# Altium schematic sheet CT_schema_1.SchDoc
size 457 x 258 mm
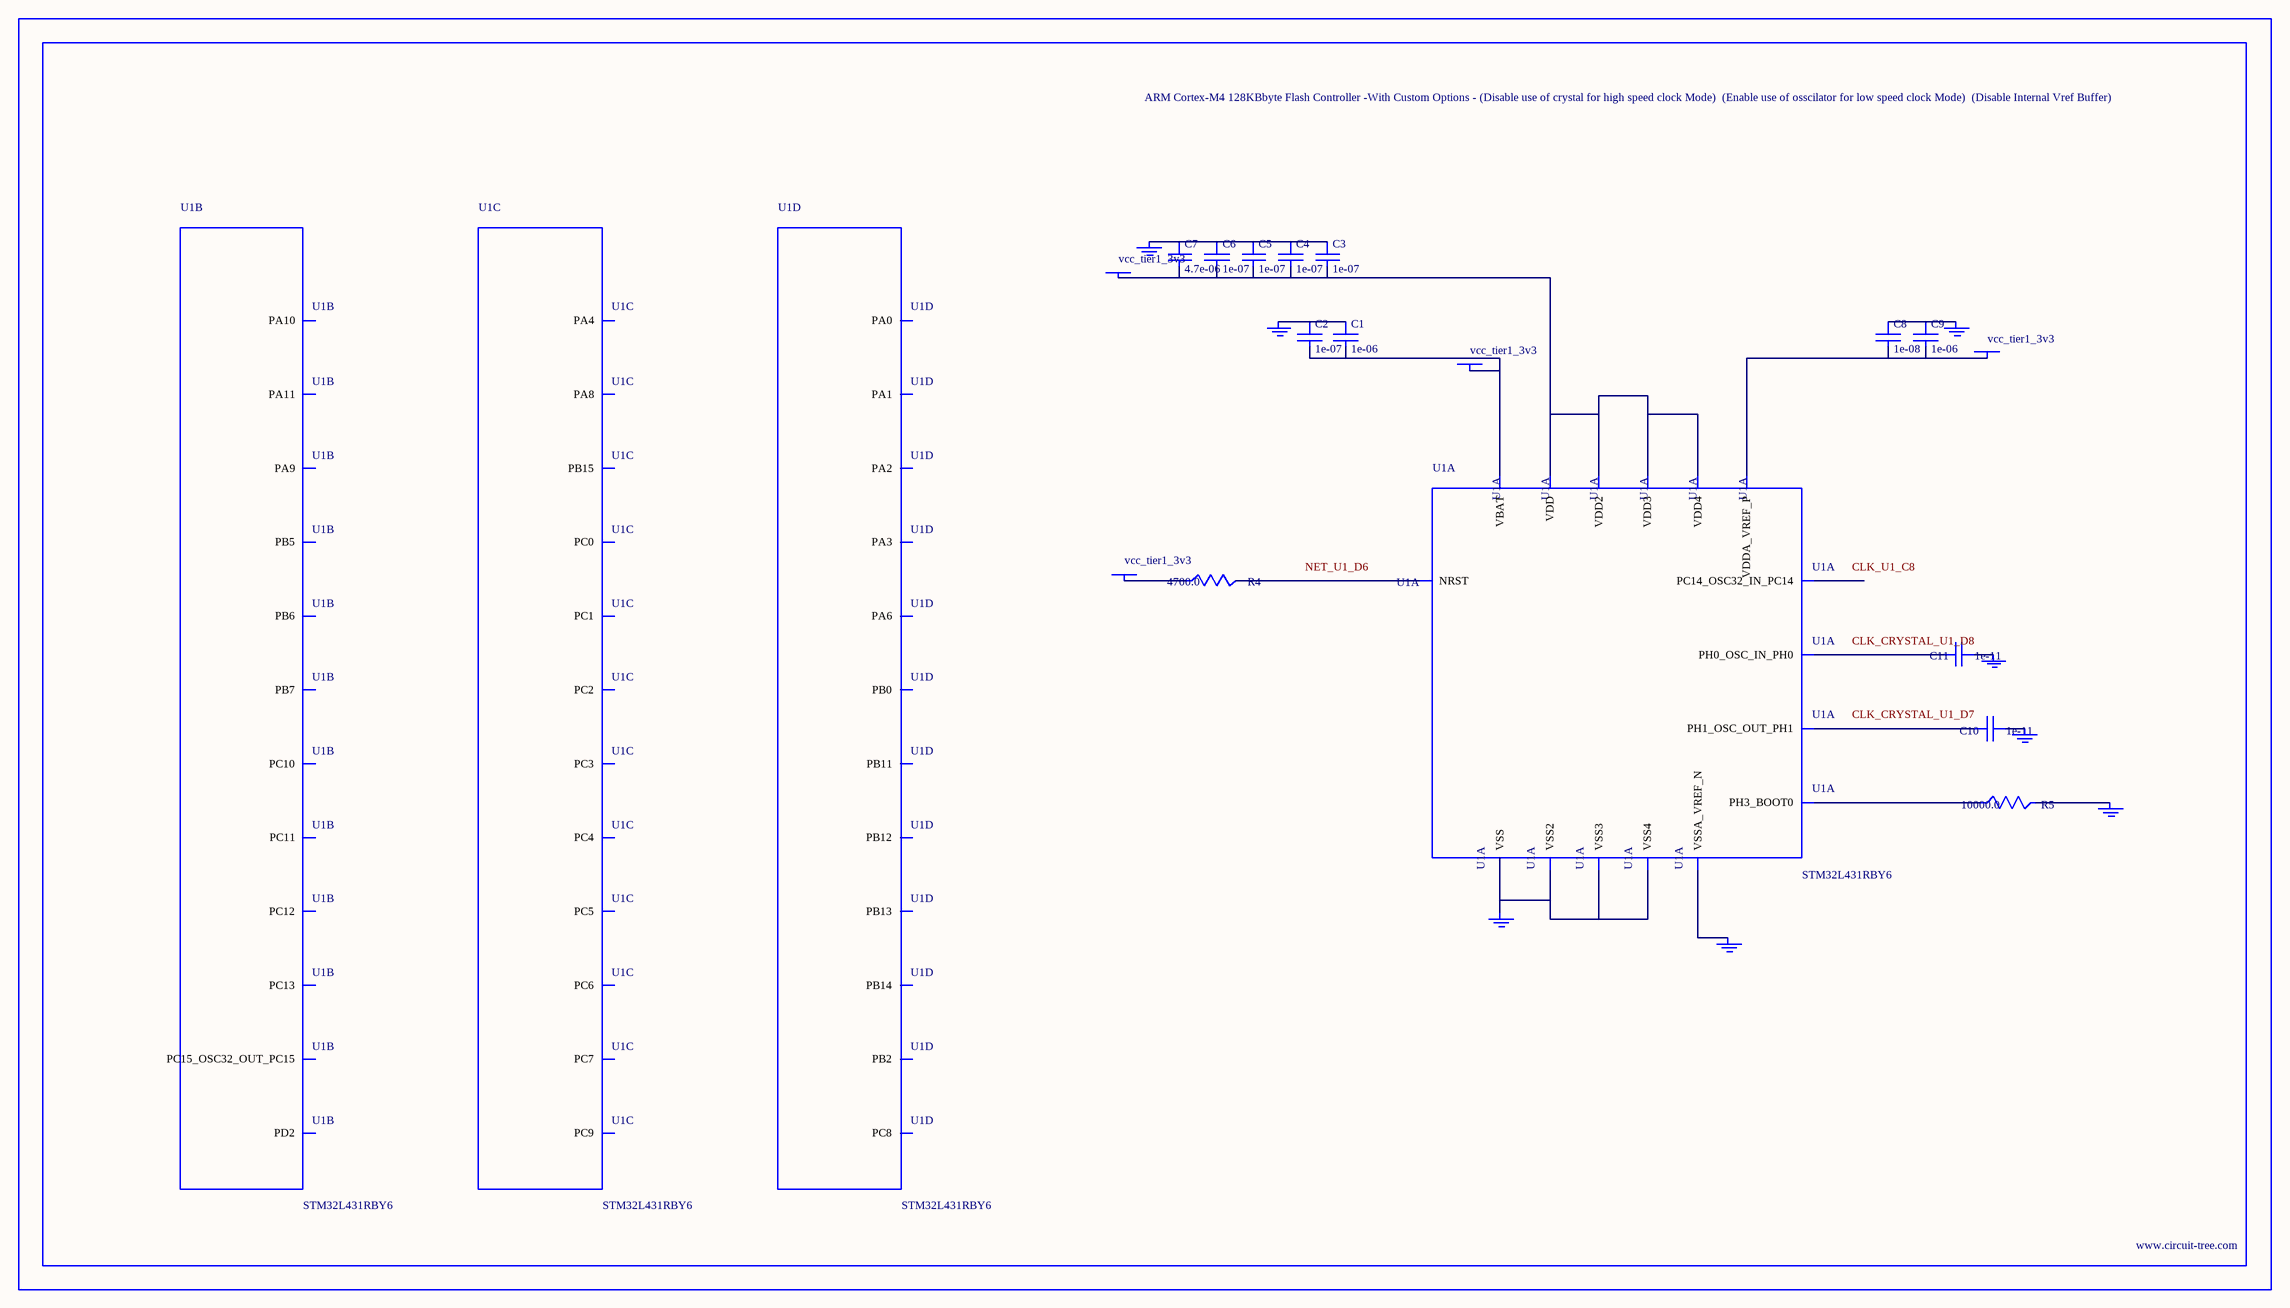
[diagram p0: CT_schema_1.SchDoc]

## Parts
BORDER0  (no value)
C1  1e-06  [C0603]
C2  1e-07  [C0603]
C3  1e-07  [C0603]
C4  1e-07  [C0603]
C5  1e-07  [C0603]
C6  1e-07  [C0603]
C7  4.7e-06  [C0603]
C8  1e-08  [C0603]
C9  1e-06  [C0603]
C10  1e-11  [C0402]
C11  1e-11  [C0402]
GND_INSTANCE_0_0  (no value)
GND_INSTANCE_0_1  (no value)
GND_INSTANCE_0_2  (no value)
GND_INSTANCE_0_3  (no value)
GND_INSTANCE_0_4  (no value)
GND_INSTANCE_0_5  (no value)
GND_INSTANCE_0_6  (no value)
GND_INSTANCE_0_7  (no value)
POWER_INSTANCE_0_0  vcc_tier1_3v3
POWER_INSTANCE_0_1  vcc_tier1_3v3
POWER_INSTANCE_0_2  vcc_tier1_3v3
POWER_INSTANCE_0_3  vcc_tier1_3v3
R4  4700.0  [R0603]
R5  10000.0  [R0603]
U1  STM32L431RBY6  [WLCSP64]  (parts A,B,C,D of 7)

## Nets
NetC1_1: C1.1 C2.1 GND_INSTANCE_0_0.0(GND)
NetC1_2: C1.2 C2.2 POWER_INSTANCE_0_0.0(PWR) U1.B7(VBAT)
NetC3_1: C3.1 C4.1 C5.1 C6.1 C7.1 GND_INSTANCE_0_1.0(GND)
NetC3_2: C3.2 C4.2 C5.2 C6.2 C7.2 POWER_INSTANCE_0_1.0(PWR) U1.A1(VDD) U1.A8(VDD2) U1.H1(VDD3) U1.H7(VDD4)
NetC8_1: C8.1 C9.1 GND_INSTANCE_0_3.0(GND)
NetC8_2: C8.2 C9.2 POWER_INSTANCE_0_2.0(PWR) U1.G8(VDDA_VREF_P)
NetC10_1: C10.1 GND_INSTANCE_0_4.0(GND)
NetC10_2: C10.2 U1.D7(PH1_OSC_OUT_PH1)
NetC11_1: C11.1 GND_INSTANCE_0_5.0(GND)
NetC11_2: C11.2 U1.D8(PH0_OSC_IN_PH0)
NetGND_INSTANCE_0_2_0: GND_INSTANCE_0_2.0(GND) R5.2
NetGND_INSTANCE_0_6_0: GND_INSTANCE_0_6.0(GND) U1.F8(VSSA_VREF_N)
NetGND_INSTANCE_0_7_0: GND_INSTANCE_0_7.0(GND) U1.A7(VSS) U1.B1(VSS2) U1.H2(VSS3) U1.H8(VSS4)
NetPOWER_INSTANCE_0_3_0: POWER_INSTANCE_0_3.0(PWR) R4.1
NetR4_2: R4.2 U1.D6(NRST)
NetR5_1: R5.1 U1.C5(PH3_BOOT0)

Not connected (* = marked no-connect by the designer): U1 A3(PC12) A4(PD2) A6(PB7) B3(PC11) B5(PB6) B8(PC13) C3(PC10) C4(PB5) C7(PC15_OSC32_OUT_PC15) C8(PC14_OSC32_IN_PC14) D1(PA9) D2(PA10) D3(PA11) D4(PC4) D5(PC0) E1(PC7) E2(PC9) E3(PA8) E4(PC5) E5(PA4) E6(PC3) E7(PC2) E8(PC1) F1(PC6) F2(PB15) F3(PC8) F4(PB0) F6(PA2) F7(PA0) G1(PB14) G2(PB13) G3(PB12) G4(PB2) G5(PA6) G6(PA3) G7(PA1) H3(PB11)

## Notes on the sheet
- Labels drawn without touching a wire or pin: CLK_CRYSTAL_U1_D7, CLK_CRYSTAL_U1_D8, CLK_U1_C8, NET_U1_D6

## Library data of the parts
BORDER0 = BORDER_PAGE0
C1 C9 = C0603C105K3RACTU
C2-C6 = 06035C104K4Z2A
C7 = GRM188R6YA475KE15D
C8 = 06035C103K4Z2A
C10 C11 = C0402C100K3GACTU
GND_INSTANCE_0_0-GND_INSTANCE_0_7 = GND
POWER_INSTANCE_0_0-POWER_INSTANCE_0_3 = PWR
R4 = RC0603JR-074K7L
R5 = RC0603JR-0710KL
